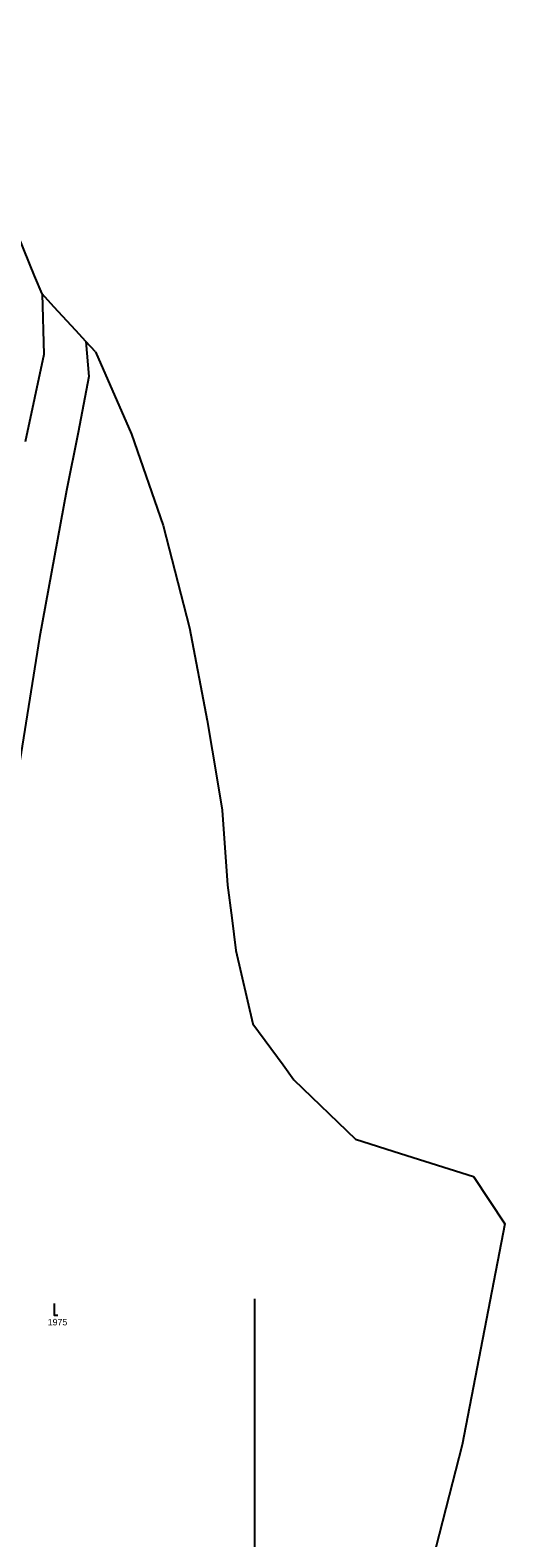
# Model space of a CAD drawing. Extents: x -802857 to -799647, y -1020285 to -1015884.
# Drawn here: x -801308.3 to -801185.1, y -1016562.1 to -1016170.3 of the extents above; entities that cross this region are included whole.
import ezdxf

# ---------------------------------------------------------------- set-up
doc = ezdxf.new("R2010")
doc.units = 0
for name, color, linetype in [('Default', 7, 'Continuous'), ('KLADY_ZMVM', 7, 'Continuous'), ('KN_HRANICE', 7, 'Continuous'), ('KN_KULTURY', 7, 'Continuous'), ('KN_PARCELY', 7, 'Continuous')]:
    doc.layers.add(name, color=color, linetype=linetype)

# ---------------------------------------------------------------- blocks, each defined once
blk = doc.blocks.new('302')
at = {"layer": 'Default'}
blk.add_lwpolyline([(0, 3), (0, 0), (1, 0)], dxfattribs=at)

msp = doc.modelspace()

# ---------------------------------------------------------------- linework, layer by layer
at = {"layer": 'KLADY_ZMVM'}
msp.add_line((-801250, -1017000), (-801250, -1016500), dxfattribs=at)
at = {"layer": 'KN_HRANICE'}
for p, q in [((-801307.14, -1016234.16), (-801333.2, -1016170.31)), ((-801305.22, -1016238.85), (-801307.14, -1016234.16)), ((-801305.22, -1016238.85), (-801304.79, -1016254.56)), ((-801302.16, -1016242.17), (-801305.22, -1016238.85)), ((-801296.43, -1016248.4), (-801302.16, -1016242.17)), ((-801293.82, -1016251.23), (-801296.43, -1016248.4)), ((-801293.82, -1016251.23), (-801293.03, -1016260.34)), ((-801291.35, -1016253.92), (-801293.82, -1016251.23)), ((-801304.79, -1016254.56), (-801309.62, -1016277.26)), ((-801291.35, -1016253.92), (-801281.96, -1016275.28)), ((-801293.03, -1016260.34), (-801295.86, -1016274.86)), ((-801295.86, -1016274.86), (-801298.85, -1016289.93)), ((-801281.96, -1016275.28), (-801273.73, -1016298.99)), ((-801298.85, -1016289.93), (-801305.9, -1016328.14)), ((-801273.73, -1016298.99), (-801266.91, -1016325.63)), ((-801266.91, -1016325.63), (-801262.33, -1016349.67)), ((-801305.9, -1016328.14), (-801311.92, -1016366.18)), ((-801262.33, -1016349.67), (-801259.75, -1016365.1)), ((-801259.75, -1016365.1), (-801258.44, -1016372.97)), ((-801258.44, -1016372.97), (-801257.05, -1016392.52)), ((-801257.05, -1016392.52), (-801255.96, -1016400.96)), ((-801255.96, -1016400.96), (-801254.86, -1016409.5)), ((-801254.86, -1016409.5), (-801250.45, -1016428.49)), ((-801250.45, -1016428.49), (-801242.64, -1016439.22)), ((-801242.64, -1016439.22), (-801239.82, -1016443.1)), ((-801239.82, -1016443.1), (-801223.83, -1016458.49)), ((-801223.83, -1016458.49), (-801212.17, -1016462.19)), ((-801212.17, -1016462.19), (-801193.22, -1016468.21)), ((-801193.22, -1016468.21), (-801185.05, -1016480.49)), ((-801185.05, -1016480.49), (-801196.12, -1016537.94)), ((-801196.12, -1016537.94), (-801207.69, -1016582.91))]:
    msp.add_line(p, q, dxfattribs=at)

# ---------------------------------------------------------------- block references
at = {"layer": 'KN_KULTURY'}
msp.add_blockref('302', (-801302.09, -1016504.19), dxfattribs=at)

# ---------------------------------------------------------------- texts
at = {"layer": 'KN_PARCELY'}
msp.add_text('1975', height=1.7, dxfattribs=at).set_placement((-801303.73, -1016506.89))

doc.saveas('drawing.dxf')
